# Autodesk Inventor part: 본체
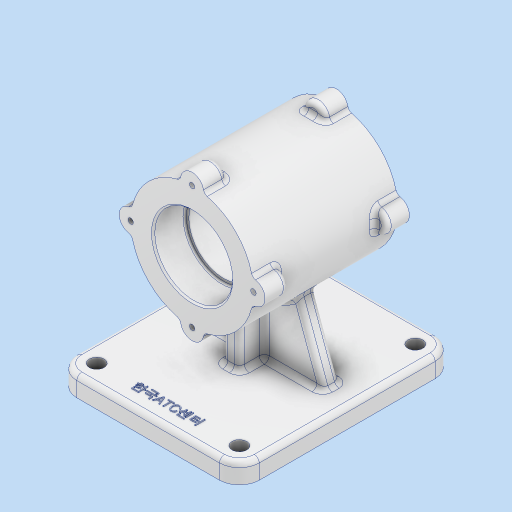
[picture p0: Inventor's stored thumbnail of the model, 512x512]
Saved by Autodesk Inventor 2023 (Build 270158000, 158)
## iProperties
Created: 2023-08
Part Number: 본체
Material: 알루미늄 6061
Document SubType Name: Modeling
Designer: asung
Density: 2.7 g/cm^3
Appearance: 알루미늄 - 평지
Mass: 1215.39 g
Surface Area: 796.917 cm^2
Volume: 450.145 cm^3
Author: asung
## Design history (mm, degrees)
sketch "스케치1"
  geometry: L1 (-43, 65)-(43, 65); L2 (55, 53)-(55, -53); L3 (43, -65)-(-43, -65); L4 (-55, -53)-(-55, 53); C1 r 4.5 at (43, 53); C2 r 4.5 at (43, -53); C3 r 4.5 at (-43, -53); C4 r 4.5 at (-43, 53); A1 r 12 centre (-43, 53) between (-43, 65) and (-55, 53); A2 r 12 centre (-43, -53) between (-55, -53) and (-43, -65); A3 r 12 centre (43, -53) between (43, -65) and (55, -53); A4 r 12 centre (43, 53) between (55, 53) and (43, 65); 4 further points
  constraints: 8 centre point, 8 end point, 8 point on circle, 8 tangent, 6 point on line, 4 coincident, 2 parallel, 1 horizontal, 1 perpendicular
  dimensions: "d0" = 110 distance of point (55, -65) point (-55, -65); "d1" = 130 distance of point (55, 65) point (55, -65); "d2" = 12 radius of A1; "d3" = 12 radius of A2; "d4" = 12 radius of A3; "d5" = 12 radius of A4; "d6" = 9 diameter of C1; "d7" = 9 diameter of C2; "d8" = 9 diameter of C3; "d9" = 9 diameter of C4
extrude "돌출1" new body sketch "스케치1" distance "d10" = 12; taper "d11" = 0 deg
node "작업 평면1"
sketch "스케치2"
  geometry: L1 (118, 12)-(118, 0) reference; L2 (118, 0)-(-12, 0) reference; L3 (-12, 0)-(-12, 12) reference; L4 (-12, 12)-(118, 12) reference; 1 further point
  node "절단 모서리 투영1"
sketch "스케치3"
  geometry: L1 (118, 12)-(118, 0) reference; L2 (118, 0)-(-12, 0) reference; L3 (-12, 0)-(-12, 12) reference; L4 (-12, 12)-(118, 12) reference; L5 (14.5, 82)-(101.5, 82); L6 (14.5, 82)-(14.5, 119); L7 (14.5, 119)-(101.5, 119); L8 (101.5, 119)-(101.5, 82); 1 further point
  constraints: 8 end point, 2 horizontal, 1 perpendicular, 1 vertical
  dimensions: "d14" = 87 distance of L5.start L5.end; "d15" = 37 distance of L5.start L6.end
revolve "회전1" sketch "스케치3" stored, may be unused: angle "d16" = 90 deg
sketch "스케치4"
  geometry: C1 r 37 at (0, 0) reference; 2 further points
  constraints: 1 coincident
hole "구멍1" sketch "스케치4" at (0, 0) diameter "d17" = 42; stored, may be unused: countersink angle "d21" = 90 deg, drill point angle "d23" = 0 deg; dims "d18" = 10, "d19" = 47, "d20" = 19, "d22" = 13
sketch "스케치5"
  geometry: C1 r 37 at (0, 0) reference; 2 further points
  constraints: 1 coincident
hole "구멍2" sketch "스케치5" at (0, 0) diameter "d24" = 42; stored, may be unused: countersink angle "d28" = 90 deg, drill point angle "d30" = 0 deg; dims "d25" = 6, "d26" = 47, "d27" = 19, "d29" = 8
fillet "모깎기1" dims "d31" = 1
chamfer "모따기1" distance "d32" = 1; stored, may be unused: second distance "d33" = 2, angle "d34" = 45 deg
fillet "모깎기2" dims "d35" = 3
sketch "스케치6"
  geometry: C1 r 37 at (0, 0) reference; C2 r 24.5 at (0, 0) reference; C3 r 7 at (0, 37); 4 further points
  constraints: 1 centre point, 1 vertical alignment, 1 other
  dimensions: "d36" = 14 diameter of C3
extrude "돌출2" join sketch "스케치6" distance "d37" = 14; taper "d38" = 0 deg
sketch "스케치7"
  geometry: C1 r 24.5 at (0, -37) reference; A1 r 37 centre (0, -37) between (36.338, -30.031) and (6.969, -0.662) reference; A2 r 7 centre (0, 0) between (6.969, -0.662) and (-6.969, -0.662) reference; A3 r 37 centre (0, -37) between (-6.969, -0.662) and (-36.338, -30.031) reference; A4 r 7 centre (-37, -37) between (-36.338, -30.031) and (-36.338, -43.969) reference; A5 r 37 centre (0, -37) between (-36.338, -43.969) and (-6.969, -73.338) reference; A6 r 7 centre (0, -74) between (-6.969, -73.338) and (6.969, -73.338) reference; A7 r 37 centre (0, -37) between (6.969, -73.338) and (36.338, -43.969) reference; A8 r 7 centre (37, -37) between (36.338, -43.969) and (36.338, -30.031) reference; 5 further points
  constraints: 4 coincident
hole "구멍3" sketch "스케치7" at (0, 0), (-37, -37), (0, -74), (37, -37) diameter "d42" = 3.242; stored, may be unused: countersink angle "d46" = 90 deg, drill point angle "d48" = 118 deg; dims "d43" = 8, "d44" = 47, "d45" = 19, "d47" = 10
node "작업 평면2"
sketch "스케치8"
  geometry: L1 (118, 9)-(118, 0) reference; L2 (118, 0)-(-12, 0) reference; L3 (-12, 0)-(-12, 9) reference; L4 (-9, 12)-(115, 12) reference; L5 (14.5, 57.5)-(15.5, 58.5) reference; L6 (15.5, 58.5)-(32.5, 58.5) reference; L7 (33.5, 59.5)-(33.5, 61) reference; L8 (33.5, 61)-(82.5, 61) reference; L9 (82.5, 61)-(82.5, 59.5) reference; L10 (83.5, 58.5)-(100.5, 58.5) reference; L11 (100.5, 58.5)-(101.5, 57.5) reference; L12 (101.5, 57.5)-(101.5, 46.621) reference; L13 (101.5, 46.621)-(91.5, 46.621) reference; L14 (91.5, 46.621)-(90.526, 45) reference; L15 (90.526, 45)-(91.5, 43.379) reference; L16 (91.5, 43.379)-(101.5, 43.379) reference; L17 (101.5, 43.379)-(101.5, 38) reference; L18 (101.5, 38)-(87.5, 38) reference; L19 (87.5, 38)-(87.5, 45) reference; L20 (87.5, 45)-(28.5, 45) reference; L21 (28.5, 45)-(28.5, 38) reference; L22 (28.5, 38)-(14.5, 38) reference; L23 (14.5, 38)-(14.5, 43.379) reference; L24 (14.5, 43.379)-(24.5, 43.379) reference; L25 (24.5, 43.379)-(25.474, 45) reference; L26 (25.474, 45)-(24.5, 46.621) reference; L27 (24.5, 46.621)-(14.5, 46.621) reference; L28 (14.5, 46.621)-(14.5, 57.5) reference; L29 (15.5, 105.5)-(14.5, 106.5) reference; L30 (14.5, 106.5)-(14.5, 117.379) reference; L31 (14.5, 117.379)-(24.5, 117.379) reference; L32 (24.5, 117.379)-(25.474, 119) reference; L33 (25.474, 119)-(24.5, 120.621) reference; L34 (24.5, 120.621)-(14.5, 120.621) reference; L35 (14.5, 120.621)-(14.5, 126) reference; L36 (14.5, 126)-(28.5, 126) reference; L37 (28.5, 126)-(28.5, 119) reference; L38 (28.5, 119)-(87.5, 119) reference; L39 (87.5, 119)-(87.5, 126) reference; L40 (87.5, 126)-(101.5, 126) reference; L41 (101.5, 126)-(101.5, 120.621) reference; L42 (101.5, 120.621)-(91.5, 120.621) reference; L43 (91.5, 120.621)-(90.526, 119) reference; L44 (90.526, 119)-(91.5, 117.379) reference; L45 (91.5, 117.379)-(101.5, 117.379) reference; L46 (101.5, 117.379)-(101.5, 106.5) reference; L47 (101.5, 106.5)-(100.5, 105.5) reference; L48 (100.5, 105.5)-(83.5, 105.5) reference; L49 (82.5, 104.5)-(82.5, 103) reference; L50 (82.5, 103)-(33.5, 103) reference; L51 (33.5, 103)-(33.5, 104.5) reference; L52 (32.5, 105.5)-(15.5, 105.5) reference; A1 r 3 centre (115, 9) between (118, 9) and (115, 12) reference; A2 r 3 centre (-9, 9) between (-9, 12) and (-12, 9) reference; A3 r 1 centre (32.5, 59.5) between (32.5, 58.5) and (33.5, 59.5) reference; A4 r 1 centre (83.5, 59.5) between (82.5, 59.5) and (83.5, 58.5) reference; A5 r 1 centre (83.5, 104.5) between (83.5, 105.5) and (82.5, 104.5) reference; A6 r 1 centre (32.5, 104.5) between (33.5, 104.5) and (32.5, 105.5) reference; 1 further point
  node "절단 모서리 투영3"
sketch "스케치9"
  geometry: L1 (-52, 53)-(-52, -53) reference; L2 (-43, -62)-(43, -62) reference; L3 (52, -53)-(52, 53) reference; L4 (43, 62)-(-43, 62) reference; L5 (5, -15)-(-5, -15); L6 (-5, -15)-(-5, 25); L7 (-5, 25)-(5, 25); L8 (5, 25)-(5, -15); L9 (5, -15)-(-5, 25); L10 (-5, -15)-(5, 25); C1 r 4.5 at (-43, -53) reference; C2 r 4.5 at (-43, 53) reference; C3 r 4.5 at (43, 53) reference; C4 r 4.5 at (43, -53) reference; A1 r 9 centre (-43, 53) between (-43, 62) and (-52, 53) reference; A2 r 9 centre (-43, -53) between (-52, -53) and (-43, -62) reference; A3 r 9 centre (43, -53) between (43, -62) and (52, -53) reference; A4 r 9 centre (43, 53) between (52, 53) and (43, 62) reference; 1 further point
  constraints: 12 end point, 2 midpoint, 2 parallel, 1 horizontal, 1 perpendicular
  dimensions: "d52" = 10 distance of L6.end L7.end; "d53" = 40 distance of L5.end L6.end
extrude "돌출3" join sketch "스케치9" stored distance "d54" = 14; taper "d55" = 0 deg
node "작업 평면3"
sketch "스케치10"
  geometry: L1 (98, 9)-(98, 0) reference; L2 (98, 0)-(-12, 0) reference; L3 (-12, 0)-(-12, 9) reference; L4 (-9, 12)-(38, 12) reference; L5 (38, 12)-(38, 45.339) reference; L6 (48, 45.339)-(48, 12) reference; L7 (48, 12)-(95, 12) reference; L8 (17.664, 55.036)-(2, 12); L9 (68.336, 55.036)-(84, 12); C1 r 21 at (43, 82) reference; A1 r 3 centre (95, 9) between (98, 9) and (95, 12) reference; A2 r 3 centre (-9, 9) between (-9, 12) and (-12, 9) reference; A3 r 37 centre (43, 82) between (48, 45.339) and (38, 45.339) reference; 1 further point
  constraints: 4 end point, 1 point on circle, 1 point on line
  dimensions: "d57" = 14 horizontal distance of L8.end L3.end; "d58" = 110 deg angle of L8 L4; "d59" = 14 distance from line of L1 L9.end; "d60" = 110 deg angle of L7 L9
  node "절단 모서리 투영5"
feature "리브1" dims "d61" = 1, "d62" = 10, "d63" = 0, "d64" = 0, "d65" = 1, "d66" = 1
feature "리브2" dims "d67" = 1, "d68" = 10, "d69" = 0, "d70" = 0, "d71" = 1, "d72" = 1
fillet "모깎기3" dims "d73" = 3
fillet "모깎기4" dims "d74" = 3
fillet "모깎기5" dims "d75" = 3
fillet "모깎기6" dims "d76" = 3
fillet "모깎기7" dims "d80" = 3
fillet "모깎기8" dims "d81" = 3
sketch "스케치11"
  geometry: L1 (-8, 22)-(-8, 13) reference; L2 (-8, 13)-(-36.716, 13) reference; L3 (-43.101, 7)-(-43.101, 3) reference; L4 (-36.716, -3)-(-8, -3) reference; L5 (-8, -3)-(-8, -12) reference; L6 (-2, -18)-(2, -18) reference; L7 (8, -12)-(8, -3) reference; L8 (8, -3)-(36.716, -3) reference; L9 (43.101, 3)-(43.101, 7) reference; L10 (36.716, 13)-(8, 13) reference; L11 (8, 13)-(8, 22) reference; L12 (2, 28)-(-2, 28) reference; L13 (-52, 53)-(-52, -53) reference; L14 (-43, -62)-(43, -62) reference; L15 (52, -53)-(52, 53) reference; L16 (43, 62)-(-43, 62) reference; L17 (-43, -65)-(43, -65) reference; C1 r 4.5 at (-43, -53) reference; C2 r 4.5 at (-43, 53) reference; C3 r 4.5 at (43, 53) reference; C4 r 4.5 at (43, -53) reference; A1 r 6 centre (-2, -12) between (-8, -12) and (-2, -18) reference; A2 r 6 centre (2, -12) between (2, -18) and (8, -12) reference; A3 r 6 centre (2, 22) between (8, 22) and (2, 28) reference; A4 r 6 centre (-2, 22) between (-2, 28) and (-8, 22) reference; A5 r 9 centre (-43, -53) between (-52, -53) and (-43, -62) reference; A6 r 9 centre (43, -53) between (43, -62) and (52, -53) reference; A7 r 9 centre (43, 53) between (52, 53) and (43, 62) reference; A8 r 9 centre (-43, 53) between (-43, 62) and (-52, 53) reference; 4 further points
  constraints: 1 midpoint, 5 other
  dimensions: "d85" = 43 distance of C4.centre point (0, -53); "d89" = 58 vertical distance of point (0, -53) point (43.101, 5)
feature "엠보싱1" sketch "스케치11" dims "d0" = 110, "d1" = 130, "d2" = 12, "d3" = 12, "d4" = 12, "d5" = 12, "d6" = 9, "d7" = 9, "d8" = 9, "d9" = 9, "d90" = 0.5, "d91" = 0
feature "Ѐ耀Ђ耀Є耀І耀Ј耀Њ耀Ќ耀Ў耀" dims "d0" = 110, "d1" = 130, "d2" = 12, "d3" = 12, "d4" = 12, "d5" = 12, "d6" = 9, "d7" = 9, "d8" = 9, "d9" = 9, "d10" = 12, "d11" = 0, "d14" = 87, "d15" = 37, "d16" = 90 deg, "d17" = 42, "d18" = 10, "d19" = 47, "d20" = 19, "d21" = 90 deg, "d22" = 13, "d23" = 0, "d24" = 42, "d25" = 6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
node "솔리드1"
pattern_circular "원형 패턴1" dims angle "d40" = 360 deg
mirror "미러1"
pattern_circular "원형 패턴2" dims angle "d78" = 360 deg
pattern_circular "원형 패턴3" dims angle "d83" = 360 deg
node "투영된 루프1"
node "투영된 루프2"
node "절단 모서리 투영2"
node "절단 모서리 투영4"
node "절단 모서리 투영6"
feature "A9D066F2-1C7D-4E18-AEED-F7BC21143FA4" dims "d17" = 42, "d18" = 10, "d19" = 47, "d20" = 19, "d21" = 90 deg, "d22" = 13, "d23" = 0
